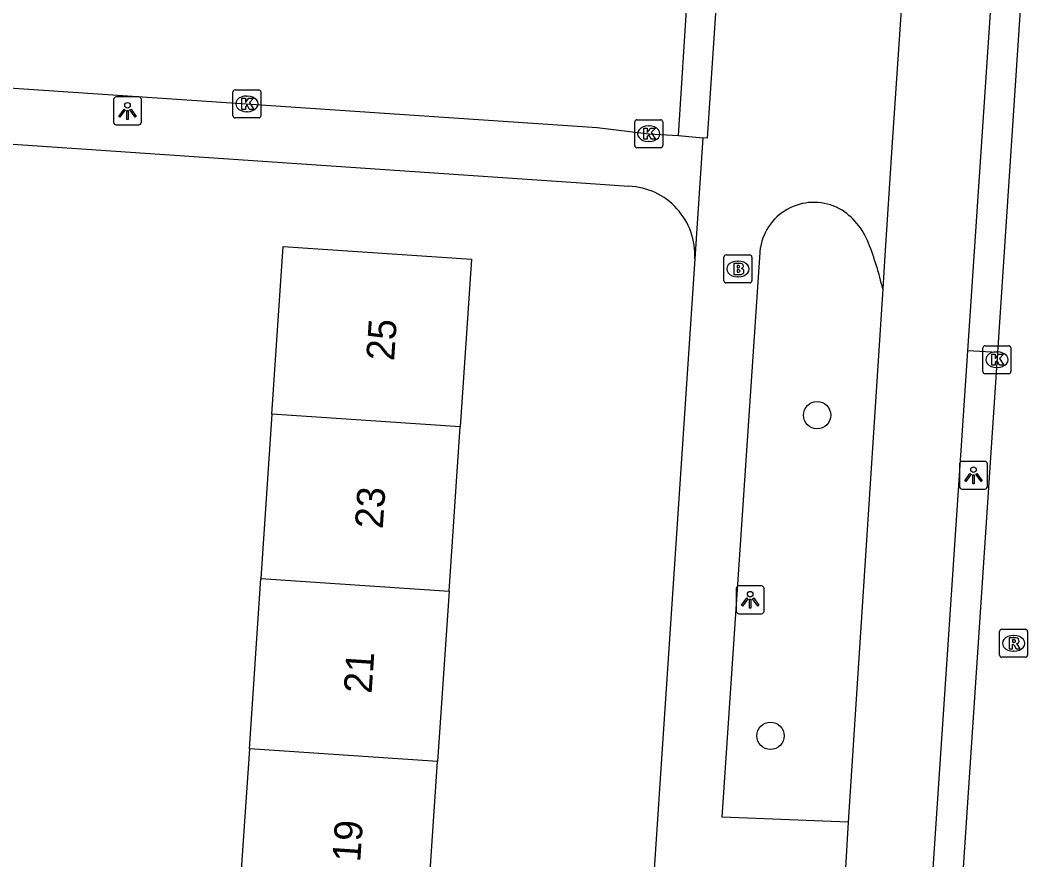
# Model space of a CAD drawing. Extents: x 161848 to 162726, y 385382 to 386521.
# Drawn here: x 161979.34 to 162015.45, y 385678.71 to 385708.77 of the extents above; entities that cross this region are included whole.
import ezdxf

# ---------------------------------------------------------------- set-up
doc = ezdxf.new("R2010")
doc.units = 0
for name, color, linetype in [('IMGEO_Boom', 7, 'Continuous'), ('IMGEO_Brandkraan', 7, 'Continuous'), ('IMGEO_Fietspad_gesloten', 7, 'Continuous'), ('IMGEO_Kolk', 7, 'Continuous'), ('IMGEO_Lichtpunt', 7, 'Continuous'), ('IMGEO_Pand', 7, 'Continuous'), ('IMGEO_Pand_nummerreeks', 7, 'Continuous'), ('IMGEO_Rijbaan_lokaal_open', 7, 'Continuous'), ('IMGEO_Rioolput', 7, 'Continuous'), ('IMGEO_Voetpad_open', 7, 'Continuous')]:
    doc.layers.add(name, color=color, linetype=linetype)

msp = doc.modelspace()

# ---------------------------------------------------------------- linework, layer by layer
at = {"layer": 'IMGEO_Boom'}
for centre in [(162007.867, 385694.629), (162006.2, 385683.148)]:
    msp.add_circle(centre, 0.489, dxfattribs=at)
at = {"layer": 'IMGEO_Brandkraan'}
for p, q in [((162004.534, 385699.438), (162004.534, 385700.29)), ((162004.609, 385700.364), (162005.461, 385700.364)), ((162005.535, 385700.29), (162005.535, 385699.438)), ((162005.022, 385700.144), (162005.047, 385700.144)), ((162005.045, 385699.584), (162005.02, 385699.584)), ((162005.461, 385699.364), (162004.609, 385699.364))]:
    msp.add_line(p, q, dxfattribs=at)
for points in [[(162004.534, 385699.438), (162004.534, 385700.29)], [(162004.609, 385700.364), (162005.461, 385700.364)], [(162005.535, 385700.29), (162005.535, 385699.438)], [(162004.882, 385700.064), (162004.882, 385699.664), (162005.095, 385699.664)], [(162005.113, 385700.064), (162004.882, 385700.064)], [(162005.061, 385699.983), (162005.007, 385699.983), (162005.007, 385699.907)], [(162005.007, 385699.907), (162005.06, 385699.907)], [(162005.069, 385699.831), (162005.007, 385699.831), (162005.007, 385699.75)], [(162005.007, 385699.75), (162005.069, 385699.75)], [(162005.461, 385699.364), (162004.609, 385699.364)]]:
    msp.add_lwpolyline(points, dxfattribs=at)
for centre, radius, start, end in [((162004.611, 385700.288), 0.0765, 91.552, 178.448), ((162004.611, 385700.288), 0.0765, 91.552, 178.448), ((162005.459, 385700.288), 0.0765, 1.552, 88.448), ((162005.459, 385700.288), 0.0765, 1.552, 88.448), ((162005.062, 385699.945), 0.0379, 267.8285, 90.9355), ((162005.117, 385699.919), 0.145, 59.4692, 91.5367), ((162005.142, 385699.966), 0.0922, 285.5137, 58.1501), ((162005.147, 385699.774), 0.105, 301.3115, 78.989), ((162005.07, 385699.79), 0.0404, 269.8759, 90.5077), ((162005.101, 385699.915), 0.251, 268.6676, 293.5347), ((162004.611, 385699.44), 0.0765, 181.552, 268.448), ((162004.611, 385699.44), 0.0765, 181.552, 268.448), ((162005.459, 385699.44), 0.0765, 271.552, 358.448), ((162005.459, 385699.44), 0.0765, 271.552, 358.448)]:
    msp.add_arc(centre, radius, start, end, dxfattribs=at)
for centre, major_axis, ratio, start_param, end_param in [((162005.021, 385699.864), (-0.387, 0.002), 0.722429, 4.712389, 7.853982), ((162005.046, 385699.864), (-0.39, 0.002), 0.717154, 1.570796, 4.712389)]:
    msp.add_ellipse(centre, major_axis=major_axis, ratio=ratio, start_param=start_param, end_param=end_param, dxfattribs=at)
at = {"layer": 'IMGEO_Fietspad_gesloten'}
for points in [[(162013.158, 385743.949), (162010.873, 385709.146), (162010.549, 385704.218), (162010.295, 385700.348), (162010.217, 385699.151)], [(162013.268, 385696.929), (162014.399, 385713.867)], [(162010.217, 385699.151), (162008.977, 385680.053)], [(162007.893, 385616.747), (162013.268, 385696.929)], [(162008.977, 385680.053), (162008.886, 385678.416)]]:
    msp.add_lwpolyline(points, dxfattribs=at)
at = {"layer": 'IMGEO_Kolk'}
for p, q in [((161986.957, 385705.349), (161986.957, 385706.201)), ((161987.032, 385706.275), (161987.884, 385706.275)), ((161987.445, 385706.055), (161987.47, 385706.055)), ((161987.958, 385706.201), (161987.958, 385705.349)), ((161987.468, 385705.495), (161987.443, 385705.495)), ((161987.884, 385705.275), (161987.032, 385705.275)), ((162001.342, 385704.28), (162001.342, 385705.132)), ((162001.417, 385705.206), (162002.269, 385705.206)), ((162001.83, 385704.986), (162001.855, 385704.986)), ((162002.343, 385705.132), (162002.343, 385704.28)), ((162002.269, 385704.206), (162001.417, 385704.206)), ((162001.853, 385704.426), (162001.828, 385704.426)), ((162013.804, 385696.187), (162013.804, 385697.039)), ((162013.879, 385697.113), (162014.731, 385697.113)), ((162014.805, 385697.039), (162014.805, 385696.187)), ((162014.292, 385696.893), (162014.317, 385696.893)), ((162014.315, 385696.333), (162014.29, 385696.333)), ((162014.731, 385696.113), (162013.879, 385696.113))]:
    msp.add_line(p, q, dxfattribs=at)
for points in [[(161986.957, 385705.349), (161986.957, 385706.201)], [(161987.032, 385706.275), (161987.884, 385706.275)], [(161987.958, 385706.201), (161987.958, 385705.349)], [(161987.278, 385705.975), (161987.401, 385705.975), (161987.401, 385705.824), (161987.531, 385705.975), (161987.695, 385705.975), (161987.549, 385705.824), (161987.702, 385705.575), (161987.55, 385705.575), (161987.465, 385705.739), (161987.401, 385705.672), (161987.401, 385705.575), (161987.278, 385705.575), (161987.278, 385705.975)], [(161987.884, 385705.275), (161987.032, 385705.275)], [(162001.342, 385704.28), (162001.342, 385705.132)], [(162001.417, 385705.206), (162002.269, 385705.206)], [(162002.343, 385705.132), (162002.343, 385704.28)], [(162001.663, 385704.906), (162001.786, 385704.906), (162001.786, 385704.755), (162001.916, 385704.906), (162002.08, 385704.906), (162001.934, 385704.755), (162002.087, 385704.506), (162001.935, 385704.506), (162001.85, 385704.67), (162001.786, 385704.603), (162001.786, 385704.506), (162001.663, 385704.506), (162001.663, 385704.906)], [(162002.269, 385704.206), (162001.417, 385704.206)], [(162013.804, 385696.187), (162013.804, 385697.039)], [(162013.879, 385697.113), (162014.731, 385697.113)], [(162014.805, 385697.039), (162014.805, 385696.187)], [(162014.125, 385696.813), (162014.248, 385696.813), (162014.248, 385696.662), (162014.378, 385696.813), (162014.542, 385696.813), (162014.396, 385696.662), (162014.549, 385696.413), (162014.397, 385696.413), (162014.312, 385696.577), (162014.248, 385696.51), (162014.248, 385696.413), (162014.125, 385696.413), (162014.125, 385696.813)], [(162014.731, 385696.113), (162013.879, 385696.113)]]:
    msp.add_lwpolyline(points, dxfattribs=at)
for centre, start, end in [((161987.034, 385706.199), 91.552, 178.448), ((161987.034, 385706.199), 91.552, 178.448), ((161987.882, 385706.199), 1.552, 88.448), ((161987.882, 385706.199), 1.552, 88.448), ((161987.034, 385705.351), 181.552, 268.448), ((161987.034, 385705.351), 181.552, 268.448), ((161987.882, 385705.351), 271.552, 358.448), ((161987.882, 385705.351), 271.552, 358.448), ((162001.419, 385705.13), 91.552, 178.448), ((162001.419, 385705.13), 91.552, 178.448), ((162002.267, 385705.13), 1.552, 88.448), ((162002.267, 385705.13), 1.552, 88.448), ((162001.419, 385704.282), 181.552, 268.448), ((162001.419, 385704.282), 181.552, 268.448), ((162002.267, 385704.282), 271.552, 358.448), ((162002.267, 385704.282), 271.552, 358.448), ((162013.881, 385697.037), 91.552, 178.448), ((162013.881, 385697.037), 91.552, 178.448), ((162014.729, 385697.037), 1.552, 88.448), ((162014.729, 385697.037), 1.552, 88.448), ((162013.881, 385696.189), 181.552, 268.448), ((162013.881, 385696.189), 181.552, 268.448), ((162014.729, 385696.189), 271.552, 358.448), ((162014.729, 385696.189), 271.552, 358.448)]:
    msp.add_arc(centre, 0.0765, start, end, dxfattribs=at)
for centre, major_axis, ratio, start_param, end_param in [((161987.444, 385705.775), (-0.387, 0.002), 0.722429, 4.712389, 7.853982), ((161987.469, 385705.775), (-0.39, 0.002), 0.717154, 1.570796, 4.712389), ((162001.829, 385704.706), (-0.387, 0.002), 0.722429, 4.712389, 7.853982), ((162001.854, 385704.706), (-0.39, 0.002), 0.717154, 1.570796, 4.712389), ((162014.291, 385696.613), (-0.387, 0.002), 0.722429, 4.712389, 7.853982), ((162014.316, 385696.613), (-0.39, 0.002), 0.717154, 1.570796, 4.712389)]:
    msp.add_ellipse(centre, major_axis=major_axis, ratio=ratio, start_param=start_param, end_param=end_param, dxfattribs=at)
at = {"layer": 'IMGEO_Lichtpunt'}
for p, q in [((161983.587, 385706.022), (161982.779, 385706.022)), ((161983.587, 385706.022), (161982.779, 385706.022)), ((161982.685, 385705.927), (161982.685, 385705.12)), ((161982.685, 385705.927), (161982.685, 385705.12)), ((161983.681, 385705.12), (161983.681, 385705.927)), ((161983.681, 385705.12), (161983.681, 385705.927)), ((161982.779, 385705.026), (161983.587, 385705.026)), ((161982.779, 385705.026), (161983.587, 385705.026)), ((162012.966, 385692.88), (162012.966, 385692.073)), ((162012.966, 385692.88), (162012.966, 385692.073)), ((162013.868, 385692.975), (162013.06, 385692.975)), ((162013.868, 385692.975), (162013.06, 385692.975)), ((162013.962, 385692.073), (162013.962, 385692.88)), ((162013.962, 385692.073), (162013.962, 385692.88)), ((162013.06, 385691.979), (162013.868, 385691.979)), ((162013.06, 385691.979), (162013.868, 385691.979)), ((162004.974, 385688.42), (162004.974, 385687.613)), ((162004.974, 385688.42), (162004.974, 385687.613)), ((162005.876, 385688.515), (162005.068, 385688.515)), ((162005.876, 385688.515), (162005.068, 385688.515)), ((162005.97, 385687.613), (162005.97, 385688.42)), ((162005.97, 385687.613), (162005.97, 385688.42)), ((162005.068, 385687.519), (162005.876, 385687.519)), ((162005.068, 385687.519), (162005.876, 385687.519))]:
    msp.add_line(p, q, dxfattribs=at)
for points in [[(161983.059, 385705.591), (161983.098, 385705.563), (161982.91, 385705.301), (161982.872, 385705.328), (161983.059, 385705.591)], [(161983.161, 385705.543), (161983.208, 385705.543), (161983.208, 385705.221), (161983.161, 385705.221), (161983.161, 385705.543)], [(161983.271, 385705.563), (161983.309, 385705.59), (161983.496, 385705.328), (161983.457, 385705.3), (161983.271, 385705.563)], [(162013.34, 385692.544), (162013.379, 385692.516), (162013.191, 385692.254), (162013.153, 385692.281), (162013.34, 385692.544)], [(162013.442, 385692.496), (162013.489, 385692.496), (162013.489, 385692.174), (162013.442, 385692.174), (162013.442, 385692.496)], [(162013.552, 385692.516), (162013.59, 385692.543), (162013.777, 385692.281), (162013.738, 385692.253), (162013.552, 385692.516)], [(162005.348, 385688.084), (162005.387, 385688.056), (162005.199, 385687.794), (162005.161, 385687.821), (162005.348, 385688.084)], [(162005.45, 385688.036), (162005.497, 385688.036), (162005.497, 385687.714), (162005.45, 385687.714), (162005.45, 385688.036)], [(162005.56, 385688.056), (162005.598, 385688.083), (162005.785, 385687.821), (162005.746, 385687.793), (162005.56, 385688.056)]]:
    msp.add_lwpolyline(points, dxfattribs=at)
for centre in [(161983.184, 385705.725), (162013.465, 385692.678), (162005.473, 385688.218)]:
    msp.add_circle(centre, 0.0994, dxfattribs=at)
for centre, start, end in [((161982.779, 385705.927), 90, 180), ((161982.779, 385705.927), 90, 180), ((161983.587, 385705.927), 0, 90), ((161983.587, 385705.927), 0, 90), ((161982.779, 385705.12), 180, 270), ((161982.779, 385705.12), 180, 270), ((161983.587, 385705.12), 270, 0), ((161983.587, 385705.12), 270, 360), ((162013.06, 385692.88), 90, 180), ((162013.06, 385692.88), 90, 180), ((162013.868, 385692.88), 0, 90), ((162013.868, 385692.88), 0, 90), ((162013.06, 385692.073), 180, 270), ((162013.06, 385692.073), 180, 270), ((162013.868, 385692.073), 270, 0), ((162013.868, 385692.073), 270, 360), ((162005.068, 385688.42), 90, 180), ((162005.068, 385688.42), 90, 180), ((162005.876, 385688.42), 0, 90), ((162005.876, 385688.42), 0, 90), ((162005.068, 385687.613), 180, 270), ((162005.068, 385687.613), 180, 270), ((162005.876, 385687.613), 270, 0), ((162005.876, 385687.613), 270, 360)]:
    msp.add_arc(centre, 0.0946, start, end, dxfattribs=at)
at = {"layer": 'IMGEO_Pand'}
for points in [[(161988.353, 385694.661), (161988.759, 385700.672), (161995.496, 385700.216), (161995.091, 385694.211)], [(161988.353, 385694.661), (161987.956, 385688.776)], [(161995.091, 385694.211), (161988.353, 385694.661)], [(161994.693, 385688.325), (161995.091, 385694.211)], [(161987.545, 385682.678), (161987.956, 385688.776)], [(161987.956, 385688.776), (161994.693, 385688.325)], [(161994.693, 385688.325), (161994.282, 385682.228)], [(161987.545, 385682.678), (161987.136, 385676.616)], [(161994.282, 385682.228), (161987.545, 385682.678)], [(161993.872, 385676.165), (161994.282, 385682.228)]]:
    msp.add_lwpolyline(points, dxfattribs=at)
at = {"layer": 'IMGEO_Rijbaan_lokaal_open'}
for points in [[(162015.447, 385713.845), (162014.322, 385696.873)], [(162002.905, 385704.639), (162003.231, 385709.718)], [(161950.969, 385708.24), (162000, 385704.93), (162001.843, 385704.706), (162002.905, 385704.639)], [(162014.322, 385696.873), (162011.334, 385651.941)]]:
    msp.add_lwpolyline(points, dxfattribs=at)
at = {"layer": 'IMGEO_Rioolput'}
for p, q in [((162014.402, 385686.034), (162014.402, 385686.886)), ((162014.477, 385686.96), (162015.329, 385686.96)), ((162015.403, 385686.886), (162015.403, 385686.034)), ((162014.89, 385686.74), (162014.915, 385686.74)), ((162014.913, 385686.18), (162014.888, 385686.18)), ((162015.329, 385685.96), (162014.477, 385685.96))]:
    msp.add_line(p, q, dxfattribs=at)
for points in [[(162014.402, 385686.034), (162014.402, 385686.886)], [(162014.477, 385686.96), (162015.329, 385686.96)], [(162015.403, 385686.886), (162015.403, 385686.034)], [(162014.991, 385686.658), (162014.739, 385686.66), (162014.739, 385686.26)], [(162014.917, 385686.579), (162014.863, 385686.579), (162014.863, 385686.498)], [(162014.739, 385686.26), (162014.863, 385686.26), (162014.863, 385686.422), (162014.874, 385686.422)], [(162014.863, 385686.498), (162014.915, 385686.498)], [(162014.921, 385686.393), (162014.992, 385686.26), (162015.132, 385686.26), (162015.067, 385686.386)], [(162015.329, 385685.96), (162014.477, 385685.96)]]:
    msp.add_lwpolyline(points, dxfattribs=at)
for centre, radius, start, end in [((162014.479, 385686.884), 0.0765, 91.552, 178.448), ((162014.479, 385686.884), 0.0765, 91.552, 178.448), ((162015.327, 385686.884), 0.0765, 1.552, 88.448), ((162015.327, 385686.884), 0.0765, 1.552, 88.448), ((162014.899, 385686.687), 0.19, 274.7715, 282.9687), ((162014.923, 385686.483), 0.0964, 77.0061, 93.1865), ((162014.937, 385686.54), 0.0378, 276.6634, 79.6772), ((162014.99, 385686.548), 0.109, 350.3612, 89.416), ((162014.988, 385686.548), 0.112, 277.5842, 350.9817), ((162014.873, 385686.369), 0.0533, 26.0293, 88.6989), ((162014.972, 385686.333), 0.108, 29.5134, 73.7905), ((162014.479, 385686.036), 0.0765, 181.552, 268.448), ((162014.479, 385686.036), 0.0765, 181.552, 268.448), ((162015.327, 385686.036), 0.0765, 271.552, 358.448), ((162015.327, 385686.036), 0.0765, 271.552, 358.448)]:
    msp.add_arc(centre, radius, start, end, dxfattribs=at)
for centre, major_axis, ratio, start_param, end_param in [((162014.889, 385686.46), (-0.387, 0.002), 0.722429, 4.712389, 7.853982), ((162014.914, 385686.46), (-0.39, 0.002), 0.717154, 1.570796, 4.712389)]:
    msp.add_ellipse(centre, major_axis=major_axis, ratio=ratio, start_param=start_param, end_param=end_param, dxfattribs=at)
at = {"layer": 'IMGEO_Voetpad_open'}
for points in [[(162003.231, 385709.718), (162004.267, 385709.569), (162003.93, 385704.551), (162003.78, 385704.564)], [(161974.338, 385704.658), (161999.588, 385702.941), (162001.131, 385702.827)], [(162002.905, 385704.639), (162003.78, 385704.564)], [(162003.78, 385704.564), (162003.492, 385700.232)], [(162008.977, 385680.053), (162004.472, 385680.234), (162005.838, 385700.634)], [(162003.492, 385700.232), (162000.908, 385661.369), (162001.053, 385661.34), (162000.699, 385656.226), (162000.549, 385656.175), (161998.429, 385625.093)], [(162014.322, 385696.873), (162013.268, 385696.929)]]:
    msp.add_lwpolyline(points, dxfattribs=at)
for centre, radius, start, end in [((162001.024, 385700.358), 2.471, 357.0762, 87.5173), ((162007.756, 385700.303), 1.946, 61.8924, 170.2146), ((162007.424, 385699.917), 2.446, 20.8783, 59.2891), ((161998.895, 385696.537), 11.62, 12.9984, 21.4625)]:
    msp.add_arc(centre, radius, start, end, dxfattribs=at)

# ---------------------------------------------------------------- texts
at = {"layer": 'IMGEO_Pand_nummerreeks'}
for s, p in [('25', (161992.724, 385696.555)), ('23', (161992.318, 385690.542)), ('21', (161991.919, 385684.642)), ('19', (161991.512, 385678.607))]:
    msp.add_text(s, height=1, rotation=86.138, dxfattribs=at).set_placement(p)

doc.saveas('drawing.dxf')
